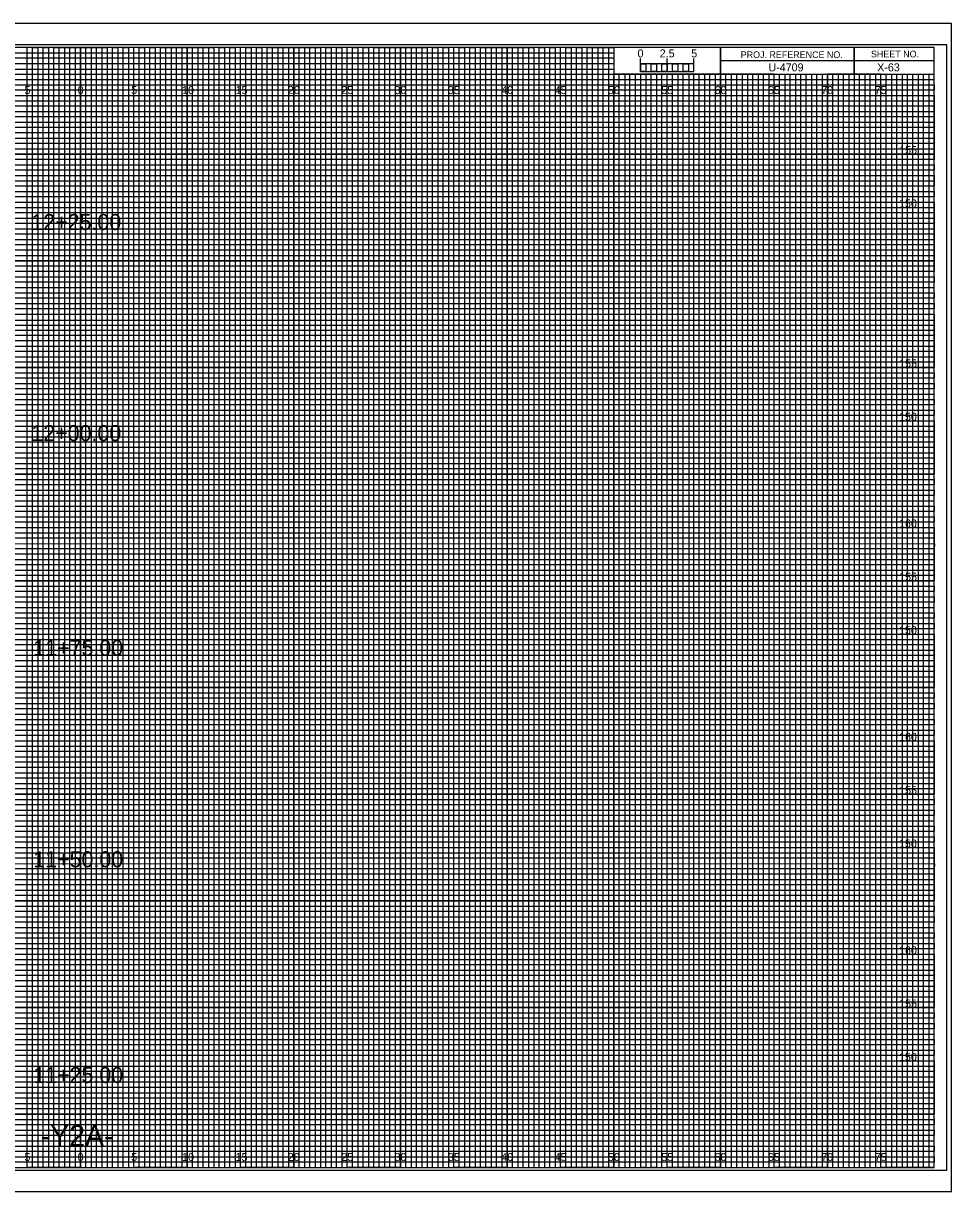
# Model space of a CAD drawing. Extents: x -7 to 162, y 108 to 217.
# Drawn here: x 74.6 to 161.7, y 107.7 to 217.2 of the extents above; entities that cross this region are included whole.
import ezdxf

# ---------------------------------------------------------------- set-up
doc = ezdxf.new("R2010")
doc.units = 0
for name, color, linetype in [('Exist CMT Pavement', 7, 'Continuous'), ('Prop CMT Pvmt Course 1 Wedge', 7, 'Continuous'), ('Prop CMT Pvmt Course 2 Wedge', 7, 'Continuous'), ('Prop CMT Pvmt Course 3 Wedge', 7, 'Continuous'), ('Prop CMT Pvmt Wedge Surface 1', 7, 'Continuous'), ('Prop CMT Pvmt Wedge Surface 2', 7, 'Continuous'), ('Prop CMT Pvmt Wedge Surface 3', 7, 'Continuous'), ('Prop CMT Shear Line', 7, 'Continuous'), ('Prop VPT Ditch Grade Left Label', 7, 'Continuous'), ('Prop XS Alignment Label', 7, 'Continuous'), ('Prop XS Bar Scale Labels', 7, 'Continuous'), ('Prop XS Elevation Labels', 7, 'Continuous'), ('Prop XS Project Number', 7, 'Continuous'), ('Prop XS Sheet Number', 7, 'Continuous'), ('Prop XS Station Labels', 7, 'Continuous'), ('Scratch_Level_3', 7, 'Continuous'), ('Scratch_Level_5', 7, 'Continuous')]:
    doc.layers.add(name, color=color, linetype=linetype)

msp = doc.modelspace()

# ---------------------------------------------------------------- linework, layer by layer
at = {"layer": 'Exist CMT Pavement'}
for p, q in [((0, 214.5), (130, 214.5)), ((130, 213.99), (0, 213.99)), ((130, 214.5), (130, 213.99)), ((0, 213.5), (130, 213.5)), ((130, 212.94), (0, 212.94)), ((130, 213.5), (130, 212.94)), ((0, 212), (160, 212))]:
    msp.add_line(p, q, dxfattribs=at)
for points in [[(0, 211.5), (135, 211.5), (160, 211.5), (160, 211), (0, 211)], [(0, 210.5), (160, 210.5), (160, 209.5), (0, 209.5)], [(0, 209), (160, 209), (160, 208.5), (0, 208.49)], [(0, 208), (160, 208), (160, 207), (0, 207)], [(0, 206.5), (160, 206.5), (160, 206), (0, 206)], [(0, 205.5), (160, 205.5), (160, 204.5), (0, 204.5)], [(0, 204), (160, 204), (160, 203.5), (0, 203.5)], [(0, 203), (160, 203), (160, 202), (0, 202)], [(0, 201.5), (160, 201.5), (160, 201), (0, 201)], [(0, 200.5), (160, 200.5), (160, 199.5), (0, 199.5)], [(0, 199), (160, 199), (160, 198.5), (0, 198.5)], [(0, 198), (160, 198), (160, 196.97), (160, 196.5), (160, 196), (0, 196)], [(0, 197), (160, 197), (160, 196.5), (0, 196.5)], [(0, 195.5), (160, 195.5), (160, 194.5), (0, 194.52)], [(0, 194.52), (160, 194.5), (160, 194), (0, 194)], [(0, 193.5), (160, 193.5), (160, 193), (0, 193)], [(0, 192), (160, 192), (160, 191.5), (0, 191.5)], [(0, 191), (160, 191), (160, 190.5), (0, 190.5)], [(-0.04, 189.44), (160, 189.44), (160, 188.94), (-0.04, 188.94)], [(0, 188.5), (160, 188.5), (160, 188), (0, 188)], [(0, 187), (160, 187), (160, 186.5), (0, 186.5)], [(0, 186), (160, 186), (160, 185.5), (0, 185.5)], [(0, 184.5), (160, 184.5), (160, 184), (0, 184)], [(0, 183.5), (160, 183.5), (160, 183), (0, 183)], [(0, 182), (160, 182), (160, 181.5), (0, 181.5)], [(0, 181), (160, 181), (160, 180.5), (0, 180.5)], [(0, 179.5), (160, 179.5), (160, 178.99), (0, 179)], [(0, 178.5), (160, 178.5), (160, 178), (0, 178)], [(0, 177), (160, 177), (160, 176.5), (0, 176.5)], [(0, 176), (160, 176), (160, 175.5), (0, 175.5)], [(0, 174.5), (160, 174.5), (160, 174), (0, 174)], [(0, 173.5), (160, 173.5), (160, 173), (0, 173)], [(0, 172), (160, 172), (160, 171.5), (0, 171.5)], [(0, 171), (160, 171), (160, 170.5), (0, 170.5)], [(0, 169.5), (160, 169.5), (160, 169), (0, 169)], [(0, 168.5), (160.03, 168.46), (160, 168), (0, 168)], [(0, 167), (160, 167), (160, 166.5), (0, 166.5)], [(0, 166), (160, 166), (160, 165.5), (0, 165.5)], [(0, 164.5), (160, 164.5), (160, 164), (0, 164)], [(0, 163.5), (160, 163.5), (160, 163), (0, 163)], [(0, 162), (160, 162), (160, 161.5), (0, 161.5)], [(0, 161), (160, 161), (160, 160.5), (0, 160.5)], [(0, 159.5), (160, 159.5), (160, 159), (0, 159)], [(0, 158.5), (160, 158.5), (160, 158), (0, 158)], [(0, 157), (160, 157), (160, 156.5), (0, 156.5)], [(0, 156), (160, 156), (160, 155.5), (0, 155.5)], [(0, 154.5), (160, 154.5), (160, 154), (0, 154)], [(0, 153.5), (160, 153.5), (160, 153), (0, 153)], [(0, 152), (160, 152), (160, 151.5), (0, 151.5)], [(0, 151), (160, 151), (160, 150.5), (0, 150.5)], [(0, 149.5), (160, 149.5), (160, 148.99), (0, 149)], [(0, 148.5), (160, 148.5), (160, 148), (0, 148)], [(0, 147), (160, 147), (160, 146.5), (0, 146.5)], [(0, 146), (160, 146), (160, 145.5), (0, 145.5)], [(0, 144.5), (160, 144.5), (160, 144), (0, 144)], [(0, 143.5), (160, 143.5), (160, 143), (0, 143)], [(0, 142), (160, 142), (160, 141.5), (0, 141.5)], [(0, 141), (160, 141), (160, 140.5), (0, 140.5)], [(0, 139.5), (160, 139.5), (160, 139), (0, 139)], [(0, 138.5), (160.03, 138.46), (160, 138), (0, 138)], [(0, 137), (160, 137), (160, 136.5), (0, 136.5)], [(0, 136), (160, 136), (160, 135.5), (0, 135.5)], [(0, 134.5), (160, 134.5), (160, 134), (0, 134)], [(0, 133.5), (160, 133.5), (160, 133), (0, 133)], [(0, 132), (160, 132), (160, 131.5), (0, 131.5)], [(0, 131), (160, 131), (160, 130.5), (0, 130.5)], [(0, 129.5), (160, 129.5), (160, 129), (0, 129)], [(0, 128.5), (160, 128.5), (160, 128), (0, 128)], [(0, 127), (160, 127), (160, 126.5), (0, 126.5)], [(0, 126), (160, 126), (160, 125.5), (0, 125.5)], [(0, 124.5), (160, 124.5), (160, 124), (0, 124)], [(0, 123.5), (160, 123.5), (160, 123), (0, 123)], [(0, 122), (160, 122), (160, 121.5), (0, 121.5)], [(0, 121), (160, 121), (160, 120.5), (0, 120.5)], [(0, 119.5), (160, 119.5), (160, 119), (0, 119)], [(0, 118.5), (160, 118.5), (160, 118), (0, 118)], [(0, 117), (160, 117), (160, 116.5), (0, 116.5)], [(0, 116), (160, 116), (160, 115.5), (0, 115.5)], [(0, 114.5), (160, 114.5), (160, 114), (0, 114)], [(0, 113.5), (160, 113.5), (160, 113), (0, 113)], [(0, 112), (160, 112), (160, 111.5), (0, 111.5)], [(0, 111), (160, 111), (160, 110.5), (0, 110.5)]]:
    msp.add_lwpolyline(points, dxfattribs=at)
at = {"layer": 'Prop CMT Pvmt Course 2 Wedge'}
for p, q in [((75, 215), (70, 215)), ((75, 110), (75, 215)), ((85, 215), (80, 215)), ((80, 215), (80, 110)), ((85, 110), (85, 215)), ((95, 215), (90, 215)), ((90, 215), (90, 110)), ((95, 110), (95, 215)), ((105, 215), (100, 215)), ((100, 215), (100, 110)), ((105, 110), (105, 215)), ((115, 215), (110, 215)), ((110, 215), (110, 110)), ((115, 110), (115, 215)), ((125, 215), (120, 215)), ((120, 215), (120, 110)), ((125, 110), (125, 215)), ((130, 215), (130, 110)), ((135, 110), (135, 212.5)), ((145, 212.5), (140, 212.5)), ((140, 212.5), (140, 110)), ((145, 110), (145, 212.5)), ((155, 212.5), (150, 212.5)), ((150, 212.5), (150, 110)), ((155, 110), (155, 212.5)), ((80, 110), (75, 110)), ((90, 110), (85, 110)), ((100, 110), (95, 110)), ((110, 110), (105, 110)), ((120, 110), (115, 110)), ((130, 110), (125, 110)), ((140, 110), (135, 110)), ((150, 110), (145, 110)), ((160, 110), (155, 110)), ((160, 110), (160, 110))]:
    msp.add_line(p, q, dxfattribs=at)
for points in [[(0, 210), (160, 210), (160, 205), (0, 205)], [(0, 200), (160, 200), (160, 195), (0, 195)], [(0, 190), (160, 190), (160, 185), (0, 185)], [(0, 180), (160, 180), (160, 175), (0, 175)], [(0, 170), (160, 170), (160, 165), (0, 165)], [(0, 160), (160, 160), (160, 155), (0, 155)], [(0, 150), (160, 150), (160, 145), (0, 145)], [(0, 140), (160, 140), (160, 135), (0, 135)], [(0, 130), (160, 130), (160, 125), (0, 125)], [(0, 120), (160, 120), (160, 115), (0, 115)]]:
    msp.add_lwpolyline(points, dxfattribs=at)
at = {"layer": 'Prop CMT Pvmt Course 3 Wedge'}
for points in [[(72.5, 110), (77.5, 110), (77.5, 215), (82.5, 215), (82.5, 110), (87.5, 110), (87.5, 215), (92.5, 215), (92.5, 110), (97.5, 110), (97.5, 215), (102.5, 215), (102.5, 110), (107.5, 110), (107.5, 215), (112.5, 215), (112.5, 110), (117.5, 110), (117.5, 215), (122.5, 215), (122.5, 110), (127.5, 110), (127.5, 215), (129.97, 215), (130, 215), (130, 212.5), (132.5, 212.5), (132.5, 110), (137.5, 110), (137.5, 212.5), (142.5, 212.5), (142.5, 110), (147.5, 110), (147.5, 212.5), (152.5, 212.5), (152.5, 110), (157.5, 110), (157.5, 212.5)], [(0, 212.5), (137.5, 212.5)], [(0, 202.5), (160, 202.5), (160, 207.5), (0, 207.5)], [(0, 192.5), (160, 192.5), (160, 197.5), (0, 197.5)], [(0, 182.5), (160, 182.5), (160, 187.5), (0, 187.5)], [(0, 172.5), (160, 172.5), (160, 177.5), (0, 177.5)], [(0, 162.5), (160, 162.5), (160, 167.5), (0, 167.5)], [(0, 152.5), (160, 152.5), (160, 157.5), (0, 157.5)], [(0, 142.5), (160, 142.5), (160, 147.5), (0, 147.5)], [(0, 132.5), (160, 132.5), (160, 137.5), (0, 137.5)], [(0, 122.5), (160, 122.5), (160, 127.5), (0, 127.5)], [(0, 112.5), (160, 112.5), (160, 117.5), (0, 117.5)]]:
    msp.add_lwpolyline(points, dxfattribs=at)
at = {"layer": 'Prop CMT Pvmt Wedge Surface 1'}
for p, q in [((152.5, 215), (152.5, 212.5)), ((152.5, 212.5), (152.5, 215)), ((160, 213.75), (140, 213.75)), ((140, 213.75), (140, 212.5)), ((140, 212.5), (160, 212.5))]:
    msp.add_line(p, q, dxfattribs=at)
for points in [[(160, 215), (0, 215), (0, 110), (160, 110)], [(140, 215), (130, 215), (130, 212.52), (140, 212.52)], [(160, 215), (140, 215), (140, 212.5), (160, 212.5)]]:
    msp.add_lwpolyline(points, close=True, dxfattribs=at)
at = {"layer": 'Prop CMT Pvmt Wedge Surface 2'}
for p, q in [((133.5, 212.5), (133, 212.5)), ((133, 212.5), (133, 110)), ((133.5, 110), (133.5, 212.5)), ((134.5, 212.5), (134, 212.5)), ((134, 212.5), (134, 110)), ((134.5, 110), (134.5, 212.5)), ((133, 110), (132.5, 110)), ((134, 110), (133.5, 110))]:
    msp.add_line(p, q, dxfattribs=at)
for points in [[(75, 110), (75.5, 110), (75.5, 215), (76, 215), (76, 110)], [(76, 110), (76.5, 110), (76.5, 215), (77, 215), (77, 110)], [(77.5, 110), (78, 110), (78, 215), (78.5, 215), (78.5, 110)], [(78.5, 110), (79, 110), (79, 215), (79.5, 215), (79.5, 110)], [(80, 110), (80.5, 110), (80.5, 215), (81, 215), (81, 110)], [(81, 110), (81.5, 110), (81.5, 215), (82, 215), (82, 110)], [(82.5, 110), (83, 110), (83, 215), (83.5, 215), (83.5, 110)], [(83.5, 110), (84, 110), (84, 215), (84.5, 215), (84.5, 110)], [(85, 110), (85.5, 110), (85.5, 215), (86, 215), (86, 110)], [(86, 110), (86.5, 110), (86.5, 215), (87, 215), (87, 110)], [(87.5, 110), (88, 110), (88, 215), (88.5, 215), (88.5, 110)], [(88.5, 110), (89, 110), (89, 215), (89.5, 215), (89.5, 110)], [(90, 110), (90.5, 110), (90.5, 215), (91, 215), (91, 110)], [(91, 110), (91.5, 110), (91.5, 215), (92, 215), (92, 110)], [(92.5, 110), (93, 110), (93, 215), (93.5, 215), (93.5, 110)], [(93.5, 110), (94, 110), (94, 215), (94.5, 215), (94.5, 110)], [(95, 110), (95.5, 110), (95.5, 215), (96, 215), (96, 110)], [(96, 110), (96.5, 110), (96.5, 215), (97, 215), (97, 110)], [(97.5, 110), (98, 110), (98, 215), (98.5, 215), (98.5, 110)], [(98.5, 110), (99, 110), (99, 215), (99.5, 215), (99.5, 110)], [(100, 110), (100.5, 110), (100.5, 215), (101, 215), (101, 110)], [(101, 110), (101.5, 110), (101.5, 215), (102, 215), (102, 110)], [(102.5, 110), (103, 110), (103, 215), (103.5, 215), (103.5, 110)], [(103.5, 110), (104, 110), (104, 215), (104.5, 215), (104.5, 110)], [(105, 110), (105.5, 110), (105.5, 215), (106, 215), (106, 110)], [(106, 110), (106.5, 110), (106.5, 215), (107, 215), (107, 110)], [(107.5, 110), (108, 110), (108, 215), (108.5, 215), (108.5, 110)], [(108.5, 110), (109, 110), (109, 215), (109.5, 215), (109.5, 110)], [(110, 110), (110.5, 110), (110.5, 215), (111, 215), (111, 110)], [(111, 110), (111.5, 110), (111.5, 215), (112, 215), (112, 110)], [(112.5, 110), (113, 110), (113, 215), (113.5, 215), (113.5, 110)], [(113.5, 110), (114, 110), (114, 215), (114.5, 215), (114.5, 110)], [(115, 110), (115.5, 110), (115.5, 215), (116, 215), (116, 110)], [(116, 110), (116.5, 110), (116.5, 215), (117, 215), (117, 110)], [(117.5, 110), (118, 110), (118, 215), (118.5, 215), (118.5, 110)], [(118.5, 110), (119, 110), (119, 215), (119.5, 215), (119.5, 110)], [(120, 110), (120.5, 110), (120.5, 215), (121, 215), (121, 110)], [(121, 110), (121.5, 110), (121.5, 215), (122, 215), (122, 110)], [(122.5, 110), (123, 110), (123, 215), (123.5, 215), (123.5, 110)], [(123.5, 110), (124, 110), (124, 215), (124.5, 215), (124.5, 110)], [(125, 110), (125.5, 110), (125.5, 215), (126, 215), (126, 110)], [(126, 110), (126.5, 110), (126.5, 215), (127, 215), (127, 110)], [(127.5, 110), (128, 110), (128, 215), (128.5, 215), (128.5, 110)], [(128.5, 110), (129, 110), (129, 215), (129.5, 215), (129.5, 110)], [(130, 110), (130.5, 110), (130.5, 212.5), (131.01, 212.5), (131.01, 110)], [(131, 110), (131.5, 110), (131.5, 212.5), (132, 212.5), (132, 110)], [(135, 110), (135.49, 110), (135.49, 212.5), (136, 212.5), (136, 110)], [(136, 110), (136.5, 110), (136.5, 212.5), (137.03, 212.5), (137.03, 110)], [(137.5, 110), (138, 110), (138, 212.5), (138.5, 212.5), (138.5, 110)], [(138.5, 110), (139, 110), (139, 212.5), (139.5, 212.5), (139.5, 110)], [(140, 110), (140.5, 110), (140.5, 212.5), (141, 212.5), (141, 110)], [(141, 110), (141.5, 110), (141.5, 212.5), (142, 212.5), (142, 110)], [(142.5, 110), (143, 110), (143, 212.5), (143.5, 212.5), (143.5, 110)], [(143.5, 110), (144, 110), (144, 212.5), (144.5, 212.5), (144.5, 110)], [(145, 110), (145.5, 110), (145.5, 212.5), (146, 212.5), (146, 110)], [(146, 110), (146.5, 110), (146.5, 212.5), (147, 212.5), (147, 110)], [(147.5, 110), (148, 110), (148, 212.5), (148.5, 212.5), (148.5, 110)], [(148.5, 110), (149, 110), (149, 212.5), (149.5, 212.5), (149.5, 110)], [(150, 110), (150.5, 110), (150.5, 212.5), (151, 212.5), (151, 110)], [(151, 110), (151.5, 110), (151.5, 212.5), (152, 212.5), (152, 110)], [(152.5, 110), (153, 110), (153, 212.5), (153.5, 212.5), (153.5, 110)], [(153.5, 110), (154, 110), (154, 212.5), (154.5, 212.5), (154.5, 110)], [(155, 110), (155.5, 110), (155.5, 212.5), (156, 212.5), (156, 110)], [(156, 110), (156.5, 110), (156.5, 212.5), (157, 212.5), (157, 110)], [(157.5, 110), (158, 110), (158, 212.5), (158.5, 212.5), (158.5, 110)], [(158.5, 110), (159, 110), (159, 212.5), (159.5, 212.5), (159.5, 110)]]:
    msp.add_lwpolyline(points, dxfattribs=at)
at = {"layer": 'Prop CMT Pvmt Wedge Surface 3'}
for p, q in [((132.5, 212.75), (132.5, 213.95)), ((132.5, 213.45), (132.5, 213.95)), ((135, 212.75), (135, 213.95)), ((137.5, 212.75), (137.5, 213.95)), ((137.5, 213.45), (137.5, 213.95))]:
    msp.add_line(p, q, dxfattribs=at)
for points in [[(137.5, 213.45), (132.5, 213.45), (132.5, 212.75), (137.5, 212.75)], [(132.5, 213.45), (133, 213.45), (133, 212.75), (132.5, 212.75)], [(133.5, 213.45), (134, 213.45), (134, 212.75), (133.5, 212.75)], [(134.5, 213.45), (135, 213.45), (135, 212.75), (134.5, 212.75)], [(135.5, 213.45), (136, 213.45), (136, 212.75), (135.5, 212.75)], [(136.5, 213.45), (137, 213.45), (137, 212.75), (136.5, 212.75)]]:
    msp.add_lwpolyline(points, close=True, dxfattribs=at)
at = {"layer": 'Prop CMT Shear Line'}
for p, q in [((161.65, 217.25), (-6.7, 217.25)), ((-6.7, 107.75), (161.65, 107.75))]:
    msp.add_line(p, q, dxfattribs=at)
at = {"layer": 'Prop VPT Ditch Grade Left Label'}
for p, q in [((75, 110), (75, 215)), ((80, 110), (80, 215)), ((85, 110), (85, 215)), ((90, 110), (90, 215)), ((95, 110), (95, 215)), ((100, 110), (100, 215)), ((105, 110), (105, 215)), ((110, 110), (110, 215)), ((115, 110), (115, 215)), ((120, 110), (120, 215)), ((125, 110), (125, 215)), ((130, 110), (130, 212.34)), ((135, 110), (135, 212.34)), ((140, 110), (140, 212.34)), ((145, 110), (145, 212.34)), ((150, 110), (150, 212.34)), ((155, 110), (155, 212.34)), ((0, 210), (160, 210)), ((0, 205), (160, 205)), ((0, 200), (160, 200)), ((0, 195), (160, 195)), ((0, 190), (160, 190)), ((0, 185), (160, 185)), ((0, 180), (160, 180)), ((0, 175), (160, 175)), ((0, 170), (160, 170)), ((0, 165), (160, 165)), ((0, 160), (160, 160)), ((0, 155), (160, 155)), ((0, 150), (160, 150)), ((0, 145), (160, 145)), ((0, 140), (160, 140)), ((0, 135), (160, 135)), ((0, 130), (160, 130)), ((0, 125), (160, 125)), ((0, 120), (160, 120)), ((0, 115), (160, 115))]:
    msp.add_line(p, q, dxfattribs=at)
at = {"layer": 'Scratch_Level_3'}
msp.add_lwpolyline([(-5.4, 109.75), (161.2, 109.75), (161.2, 215.25), (-5.4, 215.25)], close=True, dxfattribs=at)
at = {"layer": 'Scratch_Level_5'}
msp.add_lwpolyline([(-6.7, 107.75), (161.65, 107.75), (161.65, 217.25), (-6.7, 217.25)], close=True, dxfattribs=at)

# ---------------------------------------------------------------- texts
at = {"layer": 'Prop CMT Pvmt Course 1 Wedge'}
for s, p in [('5', (74.74, 210.62)), ('0', (79.73, 210.62)), ('0', (79.73, 210.62)), ('5', (84.74, 210.62)), ('10', (89.52, 210.62)), ('15', (94.53, 210.62)), ('20', (99.43, 210.62)), ('25', (104.44, 210.62)), ('30', (109.43, 210.62)), ('35', (114.44, 210.62)), ('40', (119.43, 210.62)), ('45', (124.44, 210.62)), ('50', (129.43, 210.62)), ('55', (134.44, 210.62)), ('60', (139.43, 210.62)), ('65', (144.44, 210.62)), ('70', (149.43, 210.62)), ('75', (154.44, 210.62)), ('5', (74.74, 110.62)), ('0', (79.73, 110.62)), ('0', (79.73, 110.62)), ('5', (84.74, 110.62)), ('10', (89.52, 110.62)), ('15', (94.53, 110.62)), ('20', (99.43, 110.62)), ('25', (104.44, 110.62)), ('30', (109.43, 110.62)), ('35', (114.44, 110.62)), ('40', (119.43, 110.62)), ('45', (124.44, 110.62)), ('50', (129.43, 110.62)), ('55', (134.44, 110.62)), ('60', (139.43, 110.62)), ('65', (144.44, 110.62)), ('70', (149.43, 110.62)), ('75', (154.44, 110.62))]:
    msp.add_text(s, height=0.75, dxfattribs=at).set_placement(p)
at = {"layer": 'Prop CMT Pvmt Wedge Surface 1'}
for s, p in [('PROJ. REFERENCE NO.', (141.88, 214)), ('SHEET NO.', (154.09, 214.06))]:
    msp.add_text(s, height=0.625, dxfattribs=at).set_placement(p)
at = {"layer": 'Prop CMT Pvmt Wedge Surface 3'}
msp.add_text('0', height=0.75, dxfattribs=at).set_placement((132.21, 214.06))
at = {"layer": 'Prop XS Alignment Label'}
msp.add_text('-Y2A-', height=2, dxfattribs=at).set_placement((76.26, 112))
at = {"layer": 'Prop XS Bar Scale Labels'}
for s, p in [('2.5', (134.29, 214.06)), ('5', (137.24, 214.06))]:
    msp.add_text(s, height=0.75, dxfattribs=at).set_placement(p)
at = {"layer": 'Prop XS Elevation Labels'}
for s, p in [('155', (156.73, 205)), ('150', (156.72, 200)), ('155', (156.73, 185)), ('150', (156.72, 180)), ('160', (156.72, 170)), ('155', (156.73, 165)), ('150', (156.72, 160)), ('160', (156.72, 150)), ('155', (156.73, 145)), ('150', (156.72, 140)), ('160', (156.72, 130)), ('155', (156.73, 125)), ('150', (156.72, 120))]:
    msp.add_text(s, height=0.75, dxfattribs=at).set_placement(p)
at = {"layer": 'Prop XS Project Number'}
msp.add_text('U-4709', height=0.75, dxfattribs=at).set_placement((144.48, 212.75))
at = {"layer": 'Prop XS Sheet Number'}
msp.add_text('X-63', height=0.75, dxfattribs=at).set_placement((154.67, 212.75))
at = {"layer": 'Prop XS Station Labels'}
for s, p in [('12+25.00', (75.39, 197.88)), ('12+00.00', (75.39, 178.1)), ('11+75.00', (75.57, 157.97)), ('11+50.00', (75.57, 138.15)), ('11+25.00', (75.57, 117.93))]:
    msp.add_text(s, height=1.5, dxfattribs=at).set_placement(p)

doc.saveas('drawing.dxf')
